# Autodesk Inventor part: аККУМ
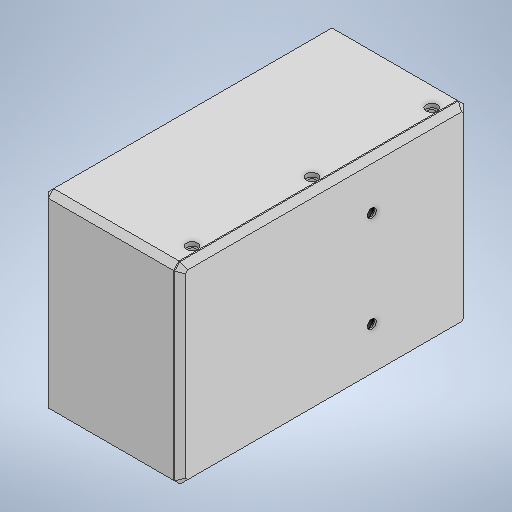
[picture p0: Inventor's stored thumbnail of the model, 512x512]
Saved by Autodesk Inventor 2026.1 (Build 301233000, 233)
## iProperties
Created: 2026-01
Part Number: аККУМ
Material: Типовые
Document SubType Name: Modeling
Designer: Yury Melnikov
Density: 1 g/cm^3
Appearance: По умолчанию
Author: Yury Melnikov
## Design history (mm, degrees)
sketch "Эскиз1"
  geometry: L1 (0, 0)-(65, 0); L2 (65, 0)-(65, 75); L3 (65, 75)-(0, 75); L4 (0, 75)-(0, 0); L5 (65, 0)-(0, 0); L6 (0, 0)-(0, -25); L7 (0, -25)-(65, -25); L8 (65, -25)-(65, 0); 1 further point
  constraints: 16 end point, 4 parallel, 2 horizontal, 2 perpendicular, 1 collinear
  dimensions: "d0" = 75 distance of L1.end L2.end; "d1" = 65 distance of L2.end L3.end; "d4" = 25 distance of L6.end L5.end
extrude "Выдавливание1" new body sketch "Эскиз1" distance "d2" = 45; taper "d3" = 0 deg
feature "Оболочка1" dims "d5" = 2.4
chamfer "Фаска1" distance "d9" = 2; stored, may be unused: second distance "d10" = 2, angle "d11" = 45 deg
sketch "Эскиз3"
  geometry: L1 (25, 63)-(25, 2) reference; L2 (23, 0)-(25, 2) reference; L3 (23, 0)-(-73, 0) reference; L4 (-75, 2)-(-73, 0) reference; L5 (-75, 2)-(-75, 63) reference; L6 (-73, 65)-(-75, 63) reference; L7 (-73, 65)-(23, 65) reference; L8 (25, 63)-(23, 65) reference; L9 (-75.4, -2.4)-(-77.4, -0.4) reference; L10 (-75.4, -2.4)-(25.4, -2.4) reference; L11 (27.4, -0.4)-(25.4, -2.4) reference; L12 (27.4, -0.4)-(27.4, 65.4) reference; L13 (25.4, 67.4)-(27.4, 65.4) reference; L14 (25.4, 67.4)-(-75.4, 67.4) reference; L15 (-77.4, 65.4)-(-75.4, 67.4) reference; L16 (-77.4, 65.4)-(-77.4, -0.4) reference; L17 (-72.917, 0.2)-(22.917, 0.2); L18 (22.917, 0.2)-(24.8, 2.083); L19 (24.8, 2.083)-(24.8, 62.917); L20 (24.8, 62.917)-(22.917, 64.8); L21 (22.917, 64.8)-(-72.917, 64.8); L22 (-72.917, 64.8)-(-74.8, 62.917); L23 (-74.8, 62.917)-(-74.8, 2.083); L24 (-74.8, 2.083)-(-72.917, 0.2); L25 (22.089, 2.2)-(-72.089, 2.2); L26 (-72.089, 2.2)-(-72.8, 2.911); L27 (-72.8, 2.911)-(-72.8, 62.089); L28 (-72.8, 62.089)-(-72.089, 62.8); L29 (-72.089, 62.8)-(22.089, 62.8); L30 (22.089, 62.8)-(22.8, 62.089); L31 (22.8, 62.089)-(22.8, 2.911); L32 (22.8, 2.911)-(22.089, 2.2); 1 further point
  constraints: 32 end point, 14 other
  dimensions: "d12" = 0.2 distance between parallel lines of L3 L17; "d13" = 2 distance between parallel lines of L17 L25
extrude "Выдавливание3" new body sketch "Эскиз3" distance "d14" = 5; taper "d15" = 0 deg
sketch "Эскиз4"
  geometry: L1 (25, 63)-(25, 2) reference; L2 (23, 0)-(25, 2) reference; L3 (23, 0)-(-73, 0) reference; L4 (-75, 2)-(-73, 0) reference; L5 (-75, 2)-(-75, 63) reference; L6 (-73, 65)-(-75, 63) reference; L7 (-73, 65)-(23, 65) reference; L8 (25, 63)-(23, 65) reference; L9 (-75.4, -2.4)-(-77.4, -0.4) reference; L10 (-75.4, -2.4)-(25.4, -2.4) reference; L11 (27.4, -0.4)-(25.4, -2.4) reference; L12 (27.4, -0.4)-(27.4, 65.4) reference; L13 (25.4, 67.4)-(27.4, 65.4) reference; L14 (25.4, 67.4)-(-75.4, 67.4) reference; L15 (-77.4, 65.4)-(-75.4, 67.4) reference; L16 (-77.4, 65.4)-(-77.4, -0.4) reference; 1 further point
extrude "Выдавливание4" join sketch "Эскиз4" distance "d16" = 2.4; taper "d17" = 0 deg
chamfer "Фаска2" distance "d18" = 2; stored, may be unused: second distance "d19" = 2, angle "d20" = 45 deg
chamfer "Фаска3" distance "d21" = 1.5; stored, may be unused: second distance "d22" = 2, angle "d23" = 45 deg
chamfer "Фаска4" distance "d24" = 0.5; stored, may be unused: second distance "d25" = 2, angle "d26" = 45 deg
sketch "Эскиз5"
  geometry: L1 (40.9, -98.317)-(40.9, -2.483) reference; L2 (45.4, -98.317)-(40.9, -98.317) reference; L3 (45.4, -2.483)-(45.4, -98.317) reference; L4 (45.4, -2.483)-(40.9, -2.483) reference; L5 (43.15, -93.817)-(43.15, -50.4); L6 (43.15, -50.4)-(43.15, -6.983); C1 r 0.75 at (43.15, -93.817); C2 r 0.75 at (43.15, -50.4); C3 r 0.75 at (43.15, -6.983); 3 further points
  constraints: 4 end point, 3 centre point, 2 collinear, 2 equal radius, 2 midpoint, 1 horizontal alignment, 1 point on line, 1 vertical
  dimensions: "d27" = 1.5 diameter of C2; "d28" = 4.5 distance from line of L2 L5.start
extrude "Выдавливание5" cut sketch "Эскиз5" distance "d29" = 75; taper "d30" = 0 deg
sketch "Эскиз8"
  geometry: L1 (-2.4, -2.4)-(98.4, -2.4) reference; L2 (-2.4, -2.4)-(72.6, -2.4); L3 (72.6, -2.4)-(72.6, 62.6); L4 (72.6, 62.6)-(-2.4, 62.6); L5 (-2.4, 62.6)-(-2.4, -2.4); L6 (74.6, -2.4)-(74.6, 62.6); L7 (72.6, -2.4)-(74.6, -2.4); L8 (72.6, 62.6)-(74.6, 62.6); L9 (74.6, 55.993)-(72.6, 55.993); L10 (72.6, 55.993)-(72.6, 64.22); L11 (72.6, 64.22)-(74.6, 64.22); L12 (74.6, 64.22)-(74.6, 55.993); 3 further points
  constraints: 22 end point, 5 parallel, 4 point on line, 3 horizontal, 2 perpendicular, 1 vertical
  dimensions: "d31" = 65 distance of L2.end L3.end; "d32" = 75 distance between parallel lines of L5 L3; "d33" = 2 distance between parallel lines of L6 L3
extrude "Выдавливание6" join sketch "Эскиз8" distance "d34" = 40; taper "d35" = 0 deg
chamfer "Фаска5" distance "d36" = 1; stored, may be unused: second distance "d37" = 2, angle "d38" = 45 deg
sketch "Эскиз9"
  geometry: L1 (0, 0)-(0, 65.8) reference; L2 (45.4, 0)-(0, 0) reference; L3 (15, 15)-(15, 50.8); C1 r 3 at (15, 15); C2 r 15 at (15, 15); C3 r 6.1 at (15, 50.8); 3 further points
  constraints: 3 centre point, 2 end point, 2 midpoint, 2 tangent, 1 coincident, 1 horizontal alignment, 1 vertical, 1 vertical alignment
  dimensions: "d39" = 6 diameter of C1; "d40" = 30 diameter of C2; "d41" = 12.2 diameter of C3
extrude "Выдавливание7" cut sketch "Эскиз9" distance "d42" = 3; taper "d43" = 0 deg
sketch "Эскиз10"
  geometry: L1 (40.4, -74)-(2.4, -74) reference; L2 (40.4, -74)-(40.4, -78) reference; L3 (2.4, -78)-(40.4, -78) reference; L4 (2.4, -98.4)-(2.4, -78) reference; L5 (45.4, -98.4)-(2.4, -98.4) reference; L6 (45.4, -2.4)-(45.4, -98.4) reference; L7 (2.4, -2.4)-(45.4, -2.4) reference; L8 (2.4, -74)-(2.4, -2.4) reference; L9 (31.65, -83.95)-(16.15, -83.95); L10 (16.15, -83.95)-(16.15, -92.45); L11 (16.15, -92.45)-(31.65, -92.45); L12 (31.65, -92.45)-(31.65, -83.95); C1 r 0.75 at (43.15, -93.817) reference; C2 r 0.75 at (43.15, -50.4) reference; C3 r 0.75 at (43.15, -6.983) reference; 5 further points
  constraints: 8 end point, 4 midpoint, 2 parallel, 1 horizontal, 1 horizontal alignment, 1 perpendicular, 1 vertical alignment
  dimensions: "d44" = 15.5 distance of L11.end L10.end; "d45" = 8.5 distance of L10.end L9.end
extrude "Выдавливание8" cut sketch "Эскиз10" distance "d46" = 3; taper "d47" = 0 deg
chamfer "Фаска6" distance "d48" = 0.7; stored, may be unused: second distance "d49" = 2, angle "d50" = 45 deg
chamfer "Фаска7" distance "d51" = 0.5; stored, may be unused: second distance "d52" = 2, angle "d53" = 45 deg
sketch "Эскиз11"
  geometry: C1 r 0.75 at (43.15, -6.983) reference; C2 r 0.75 at (43.15, -50.4) reference; C3 r 0.75 at (43.15, -93.817) reference; C4 r 2 at (43.15, -6.983); C5 r 2 at (43.15, -50.4); C6 r 2 at (43.15, -93.817); 1 further point
  constraints: 3 centre point, 2 equal radius
  dimensions: "d54" = 4 diameter of C4
extrude "Выдавливание9" cut sketch "Эскиз11" distance "d55" = 1.4; taper "d56" = 0 deg
chamfer "Фаска8" distance "d57" = 0.5; stored, may be unused: second distance "d58" = 2, angle "d59" = 45 deg
node "РабПлоскость2"
mirror "Зеркальное отражение1"
node "РабПлоскость3"
sketch "Эскиз12"
  geometry: L1 (2, 61)-(2, 0) reference; L2 (2, 0)-(2, 61) reference; L3 (2, 9.6)-(2, 15.6) reference; L4 (2, 42.3)-(2, 54.5) reference; L5 (2, 49)-(-4.5, 49); L6 (-4.5, 49)-(-4.5, 42); L7 (-4.5, 42)-(-2.5, 42); L8 (-2.5, 42)-(-2.5, 47); L9 (-2.5, 47)-(2, 47); L10 (-2.5, 47)-(-2.5, 49); L11 (2, 30.5)-(16.292, 30.5); L12 (2, 18.7)-(2, 6.5); L13 (2, 12)-(-4.5, 12); L14 (-4.5, 12)-(-4.5, 19); L15 (-4.5, 19)-(-2.5, 19); L16 (-2.5, 19)-(-2.5, 14); L17 (-2.5, 14)-(2, 14); L18 (-2.5, 14)-(-2.5, 12); 6 further points
  constraints: 28 end point, 9 symmetric about line, 8 point on line, 3 horizontal, 3 perpendicular, 2 midpoint, 1 vertical
  dimensions: "d62" = 5 distance of L7.end L8.end; "d63" = 2 distance of L6.end L7.end; "d64" = 4.5 distance of L8.end L9.end; "d65" = 33 distance from line of L17 point (-0.25, 47)
extrude "Выдавливание10" join sketch "Эскиз12" distance "d66" = 6; taper "d67" = 0 deg
sketch "Эскиз13"
  geometry: L1 (37, 16.4)-(37, 21.4) reference; L2 (37, 21.4)-(31, 21.4) reference; L3 (31, 16.4)-(31, 21.4) reference; L4 (37, 16.4)-(31, 16.4) reference; L5 (37, 44.4)-(37, 49.4) reference; L6 (37, 49.4)-(31, 49.4) reference; L7 (31, 44.4)-(31, 49.4) reference; L8 (37, 44.4)-(31, 44.4) reference; L9 (27.35, 16.65)-(40.65, 16.65); L10 (40.65, 16.65)-(40.65, 49.15); L11 (40.65, 49.15)-(27.35, 49.15); L12 (27.35, 49.15)-(27.35, 16.65); L13 (31, 21.4)-(31, 44.4); C1 r 1.65 at (30.35, 41.15); C2 r 1.65 at (30.35, 36.15); C3 r 1.65 at (30.35, 31.15); C4 r 1.65 at (30.35, 26.15); C5 r 2.1 at (35.65, 41.65); 5 further points
  constraints: 10 end point, 5 centre point, 4 midpoint, 2 parallel, 2 vertical, 1 horizontal, 1 horizontal alignment, 1 perpendicular, 1 vertical alignment, 6 other
  dimensions: "d68" = 32.5 distance of L11.end L9.start; "d69" = 13.3 distance of L9.start L9.end; "d70" = 3 horizontal distance of C1.centre L11.end; "d71" = 8 vertical distance of L11.end C1.centre; "d72" = 3.3 diameter of C1; "d75" = 5 distance of C1.centre C2.centre; "d80" = 4.2 diameter of C5; "d81" = 7.5 vertical distance of L10.end C5.centre; "d82" = 5 distance from line of L10 C5.centre
extrude "Выдавливание11" cut sketch "Эскиз13" distance "d83" = 6; taper "d84" = 0 deg
chamfer "Фаска9" distance "d85" = 0.5; stored, may be unused: second distance "d86" = 2, angle "d87" = 45 deg
chamfer "Фаска10" distance "d88" = 3; stored, may be unused: second distance "d89" = 2, angle "d90" = 45 deg
sketch "Эскиз14"
  geometry: L1 (-77.4, 65.4)-(-77.4, -0.4) reference; L2 (-7.94, 49.9)-(-7.94, 15.1); L3 (25.4, 64.572)-(25.4, 0.428) reference; C1 r 1.6 at (-7.94, 49.9); C2 r 1.6 at (-7.94, 15.1); 3 further points
  constraints: 2 centre point, 2 end point, 2 midpoint, 1 equal radius, 1 horizontal alignment, 1 vertical, 1 vertical alignment
  dimensions: "d91" = 69.46 distance from line of L1 L2.start; "d92" = 38 dimension on C1 C2; "d93" = 3.2 diameter of C1
extrude "Выдавливание12" cut sketch "Эскиз14" distance "d94" = 10; taper "d95" = 0 deg
chamfer "Фаска11" distance "d96" = 1.8; stored, may be unused: second distance "d97" = 2, angle "d98" = 45 deg
node "Твердое тело1"
node "Спроецированная петля2"
node "Твердое тело2"
node "Спроецированная петля3"
node "Спроецированная петля4"
node "Спроецированная петля5"
node "Спроецированная петля6"
node "Спроецированная петля7"
node "Спроецированная петля8"
node "Эскиз — прямоугольный массив1" dims "d75" = 5, "d78" = 10
other parameters: "d60" = 8
